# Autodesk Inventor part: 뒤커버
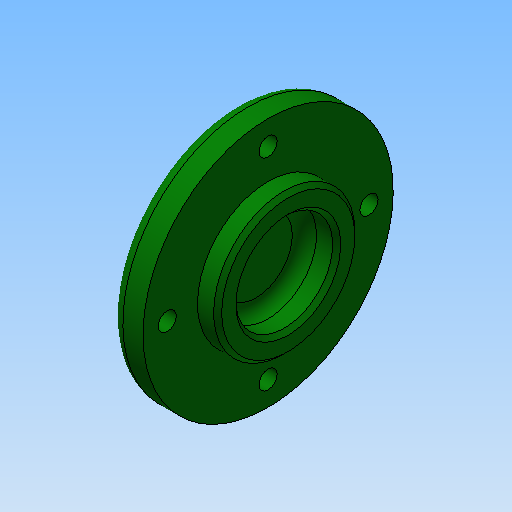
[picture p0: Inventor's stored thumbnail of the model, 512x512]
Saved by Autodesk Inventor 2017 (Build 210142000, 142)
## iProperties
Created: 2015-12
Part Number: 뒤커버
Document SubType Name: Modeling
Designer: mdu
Density: 2.71 g/cm^3
Material: 알루미늄 6061
Mass: 72.2029 g
Surface Area: 89.061 cm^2
Volume: 26.6431 cm^3
Appearance: 진녹색
Author: mdu
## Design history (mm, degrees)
sketch "스케치1"
  geometry: L1 (-8, 0)-(8, 0); L2 (-8, 0)-(-8, 15.5); L3 (-8, 15.5)-(-5, 18.5); L4 (-5, 18.5)-(-5, 31); L5 (-5, 31)-(3, 31); L6 (3, 31)-(3, 17.5); L7 (3, 17.5)-(8, 17.5); L8 (8, 17.5)-(8, 0); 2 further points
  constraints: 16 end point, 4 parallel, 2 perpendicular, 1 coincident, 1 horizontal, 1 midpoint
  dimensions: "d0" = 16 distance of L1.start L1.end; "d1" = 62 diameter of L5 L1; "d2" = 35 diameter of L7 L1; "d3" = 37 diameter of L3.end L1; "d5" = 8 distance of L4.end L5.end; "d34" = 135 deg angle of L4 L3; "d36" = 5 distance of L6.end L7.end
revolve "회전1" sketch "스케치1" stored, may be unused: angle "d6" = 90 deg
sketch "스케치2" dims "d32" = 50
  geometry: 3 further points
  constraints: 2 vertical alignment, 1 coincident, 2 other
hole "구멍1" sketch "스케치2" at (0, 25) diameter "d8" = 4.5; stored, may be unused: countersink angle "d12" = 90 deg, drill point angle "d14" = 118 deg; dims "d9" = 6, "d10" = 8, "d11" = 4.4, "d13" = 8
hole "구멍2" diameter "d20" = 24; stored, may be unused: countersink angle "d24" = 90 deg, drill point angle "d26" = 0 deg; dims "d18" = 10, "d19" = 10, "d21" = 6, "d22" = 8, "d23" = 4.4, "d25" = 8
fillet "모깎기1" dims "d27" = 3
fillet "모깎기2" dims "d28" = 3
chamfer "모따기1" distance "d29" = 1; stored, may be unused: second distance "d30" = 2, angle "d31" = 45 deg
node "솔리드1"
pattern_circular "원형 패턴1" dims angle "d16" = 360 deg
